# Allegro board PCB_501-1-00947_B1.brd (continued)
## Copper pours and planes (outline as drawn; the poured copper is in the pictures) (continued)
VDD_1V35 on BOTTOM (solid shape): 63.98,92.52 63.99,92.5 64,92.48 64.01,92.45 64.01,92.42 64,92.39 63.98,92.37 63.95,92.35 63.91,92.31 63.88,92.27 63.87,92.25 63.43,91.81 63.09,92.15 63.09,92.48 63.28,92.68 63.28,92.75 62.23,93.81 61.93,93.81 61.62,93.49 61.61,93.49 61.34,93.22 61.28,93.22 60.88,93.62 60.65,93.62 59,91.98 58.71,91.98 58.05,92.63 58.05,92.75 58.15,92.75 59.65,94.24 60.69,94.24 60.69,94.22 60.7,94.17 60.71,94.12 60.74,94.08 60.77,94.04 60.8,94.01 60.84,93.98 60.89,93.96 60.93,93.95 60.98,93.94 61.03,93.94 61.08,93.95 61.13,93.97 61.17,93.99 61.21,94.02 61.24,94.06 61.27,94.1 61.29,94.15 61.3,94.2 61.3,94.24 61.3,94.29 61.29,94.34 61.27,94.39 61.24,94.43 61.21,94.46 61.17,94.5 61.13,94.52 61.08,94.54 61.03,94.55 60.98,94.55 60.93,94.54 60.89,94.53 60.84,94.51 60.8,94.48 60.77,94.45 60.74,94.41 60.71,94.36 60.7,94.32 60.69,94.27 60.69,94.24 59.65,94.24 60.77,95.36 61.13,95.36
VDD_1V35 on TOP: 19.91,73.15 19.27,73.79 19.27,76.33 19.52,76.58 22.06,76.58 22.32,76.33 26.26,76.33 26.76,75.82 26.76,69.34 26.38,68.96 20.41,68.96 19.91,69.47
VDD_1V35 on TOP: 82.64,114.94 85.69,114.94 85.82,115.06 85.82,116.2 85.69,116.33 82.52,116.33 82.39,116.2 82.39,115.19
VDD_1V35 on L3_INT_1: 86.07,113.58 84.72,112.23 82.71,112.23 82.17,111.69 82.17,108.43 81.94,108.2 71.34,108.2 70.58,108.97 70.58,116.31 70.76,116.49 85.77,116.49 86.07,116.19
VDD_1V35 on L4_PWR_1: 38.34,88.95 34.89,85.5 34.89,79.12 25.62,69.85 20.16,69.85 19.78,70.23 19.78,74.42 27.85,82.49 27.85,99.86 39.5,111.51 45.73,111.51 46.26,112.03 55.93,121.71 68.59,121.71 69.73,120.56 75.33,114.97 75.33,100.22 67.74,92.64 66.09,90.98 66.1,90.97 66.1,89.7 65.95,89.56 65.24,89.56 64.66,90.13 57.7,90.13 57.11,90.72 54.42,90.72 52.65,88.95
VDD_1V35_L2 on TOP: 15.08,81.46 15.08,80.9 15.33,80.64 17.24,80.64 17.37,80.77 17.37,81.92 17.32,81.92 16.85,82.39 16.85,82.86 16.49,83.22 16.38,83.46 16.38,84.32 16.18,84.32 16.18,83.09 16.08,82.68 15.91,82.52 15.64,82.52 15.5,82.38 15.5,81.88
VDD_1V35_SNS on TOP: 17.49,80.14 15.21,80.14 15.08,80.01 15.08,74.3 15.46,73.91 18.51,73.91 18.76,74.17 18.76,79.63 18.64,79.76 17.87,79.76
VDD_3V3 on TOP: 32.61,50.93 30.45,50.93 30.19,51.18 30.19,52.83 30.19,52.83 30.19,53.49 30.32,53.62 32.65,53.62 32.73,53.54 32.73,51.05
VDD_3V3 on TOP: 95.85,57.26 90.05,57.26 90.05,59.36 87.3,59.36 87.3,59.46 85.38,59.46 85.38,48.68 95.85,48.68
VDD_3V3 on TOP: 85.82,109.98 84.04,109.98 83.91,109.86 83.91,108.84 83.79,108.71 83.28,108.71 83.15,108.84 83.15,109.86 83.02,109.98 82.9,109.98 82.77,110.11 82.77,111.38 82.9,111.51 83.91,111.51 84.04,111.63 85.69,111.63 85.95,111.38 85.95,110.11
VDD_3V3 on TOP: 119.2,20.57 119.2,21.84 119.2,21.68 120.48,21.68 120.48,21.84 123.16,21.84 123.54,22.22 125.82,22.22 125.95,22.1 125.95,20.83 125.7,20.57 ; 1 cut-out
VDD_3V3 on TOP: 15.59,94.87 14.83,94.87 13.56,93.6 6.57,93.6 6.19,93.98 6.19,98.81 6.7,99.31 15.08,99.31 15.97,98.42 15.97,95.25
VDD_3V3 on TOP: 16.73,6.99 12.67,6.99 12.29,7.37 12.29,30.23 13.17,31.11 17.62,31.11 18.51,30.23 18.51,8.76
VDD_3V3 on BOTTOM: 71.59,56.13 71.59,56.39 72.36,57.15 72.36,59.05 72.23,59.18 72.23,59.94 72.61,60.33 72.61,60.83 72.23,61.21 71.21,61.21 69.18,59.18 69.18,56.64 68.29,55.75 68.29,55.24 69.44,54.1 69.56,54.1
VDD_3V3 on BOTTOM: 21.05,40.26 24.99,40.26 25.49,40.77 25.49,41.78 25.24,42.04 24.1,42.04 23.84,42.29 23.33,42.29 23.33,41.91 23.08,41.66 22.56,41.66 21.93,42.29 21.18,42.29 20.92,42.04 20.92,40.39
VDD_3V3 on BOTTOM: 95.62,57.09 93.52,57.09 93.52,55.85 94.3,55.85 94.3,54.66 94.33,54.66 94.33,53.95 96.59,53.95 96.59,56.03 95.62,56.03
VDD_3V3 on L3_INT_1: 122.65,128.02 123.94,126.72 123.94,119.7 121.2,116.97 107.44,116.97 106.43,115.96 106.43,111.39 105.54,110.51 89.09,110.51 86.85,108.26 82.73,108.26 82.51,108.47 82.51,111.3 83.09,111.88 85.13,111.88 86.64,113.4 86.64,116.44 86.12,116.97 67.4,116.97 62.7,121.67 56.14,121.67 51.48,117.01 50.05,117.01 46.45,113.41 46.45,108.08 45.94,107.57 45.94,101.76 43.62,99.44 43.6,99.44 42.37,98.21 33.09,98.21 30,95.12 30,90.86 29.69,90.55 22.7,90.55 22.04,91.22 22.04,93.68 21.75,93.97 20,93.97 18.7,92.67 14.62,92.67 14.32,92.96 6.82,92.96 5.68,94.11 5.68,111.12 5.68,111.13 5.68,124.6 9.1,128.02
VDD_3V3 on L4_PWR_1: outline of 93 points within 0.83,0.86 129.15,99.95
VDD_3V3 on L5_PWR_2: 97.63,82.8 127.28,82.8 128.19,83.71 128.19,125.03 125.55,127.66 98.37,127.66 96.68,125.97 96.68,83.76
VDD_3V3 on L5_PWR_2: 63.89,51.48 30.66,51.48 30.45,51.69 30.45,59.82 33.75,63.12 33.75,66.69 39.36,66.69 44.67,72.01 44.67,79.92 48.99,84.24 50.46,84.24 52.52,82.19 52.52,81.3 53.17,80.66 55.96,80.66 61.07,75.55 62.56,75.55 70.01,82.99 73.75,79.25 73.75,75.95 77.56,72.14 92.04,72.14 92.3,71.88 92.3,69.22 92.04,68.96 81.37,68.96
VDD_3V3 on L6_INT_2: 39.97,84.71 27.36,84.71 27.02,85.05 27.02,89.53 26.51,90.04 23.72,90.04 23.08,90.68 23.08,93.85 23.84,94.61 33.24,94.61 33.99,93.86 33.99,89.43 34.21,89.21 40.05,89.21 40.23,89.04 40.23,84.96
VDD_3V3 on L6_INT_2: 65.12,83.82 65.75,84.45 65.75,85.47 64.99,86.23 64.74,86.23 63.09,84.58 63.09,83.95 63.21,83.82
VDD_3V3_L4A on TOP: 20.54,90.93 20.54,92.75 20.41,92.88 19.77,92.88 19.68,92.8 19.68,91.43 18.58,90.32 18.58,89.41 19.02,89.41
VDD_3V3_L4B on TOP: 19.09,90.99 19.09,92.78 18.98,92.89 18.2,92.89 18.13,92.82 18.13,90.34 18.18,90.27 18.18,89.41 18.38,89.41 18.38,90.21 18.42,90.28 18.51,90.41
VDD_3V3_LCD on TOP: 22.83,45.97 19.78,45.97 19.14,45.34 16.48,45.34 16.35,45.47 16.35,49.53 15.97,49.91 14.83,49.91 14.44,49.53 14.44,44.45 15.08,43.81 22.83,43.81 23.21,44.2 23.21,45.59
VDD_3V3_LCD on BOTTOM: 19.78,44.96 19.78,46.74 19.91,46.86 22.83,46.86 22.95,46.74 23.09,44.39 23.09,42.19 23,42.1 22.59,42.1 22.15,42.55 21.18,42.55 20.79,42.93 20.79,43.94
VDD_3V3_LCD on L4_PWR_1: 0.98,61.09 0.84,60.94 0.84,38.83 1.57,38.1 15.21,38.1 15.97,38.86 15.97,43.18 15.97,43.18 15.97,45.99 17.11,47.13 17.11,49.02 16.09,50.04 10.68,50.04 9.03,51.69 9.03,60.94 8.89,61.09 ; 1 cut-out
VDD_3V3_PERI on TOP: 28.29,48.51 28.67,48.13 32.22,48.13 32.35,48.26 32.35,50.55 32.22,50.67 30.19,50.67 30.07,50.55 30.07,49.91 29.94,49.78 28.8,49.78 28.29,49.28
VDD_3V3_PERI on TOP: 63.19,40 63.19,38.4 63.52,38.07 66.32,38.07 66.59,38.35 66.59,39.95 66.42,40.12 63.31,40.12
VDD_3V3_PERI on TOP: 106.65,83.06 106.77,83.19 129.36,83.19 129.36,67.93 128.74,67.31 122.65,67.31 122.14,67.82 122.14,70.23 122.65,70.74 123.66,70.74 123.92,70.99 123.92,73.66 123.66,73.91 120.62,73.91 116.93,77.6 108.04,77.6 107.79,77.85 92.32,77.85 91.85,78.31 91.85,82.59 92.32,83.06
VDD_3V3_PERI on BOTTOM: 93.95,81.2 93.95,83.86 93.57,84.24 92.13,84.24 91.99,84.1 91.99,81.18 92.23,80.94 93.69,80.94
VDD_3V3_PERI on L5_PWR_2: 30.03,49.66 30.03,44.36 30.03,44.36 30.25,44.14 45.66,44.14 46.93,42.87 46.93,41.51 48.3,40.13 61.18,40.13 61.82,39.5 61.82,30.31 62.54,29.59 98.65,29.59 98.65,36.73 106.65,36.73 106.65,29.59 127.18,29.59 128.11,30.53 128.11,81.7 127.46,82.35 97.69,82.35 96.35,81 96.35,77.48 95.77,76.9 92.84,76.9 92.55,76.61 92.55,68.83 92.11,68.39 81.56,68.39 63.49,50.31 30.69,50.31
VDD_3V3_SD on TOP: 11.91,87.85 12.1,88.04 12.39,88.04 12.39,88.04 12.87,88.04 12.95,87.95 12.95,87.4 13,87.24 13.08,87.17 13.93,87.17 13.93,86.97 12.72,86.97 12.43,87.26 11.96,87.26 11.91,87.31
VDD_3V3_SNS on TOP: 17.98,89.41 17.78,89.41 17.78,90.22 16.48,91.51 16.48,97.92 16.86,98.3 20.29,98.3 20.54,98.04 20.54,93.98 20.16,93.6 18.64,93.6 18.03,92.99 18.03,90.36 17.98,90.24
VDD_5V on TOP: 4.79,83.06 4.77,83.08 4.77,87.02 4.54,87.25 1.49,87.25 0.98,86.74 0.98,81.66 0.99,81.66 0.99,80.3 1.27,80.01 7.2,80.01 7.52,80.33 7.52,82.2 7.45,82.27 5.58,82.27
VDD_5V on BOTTOM: 10,40.26 10,39.75 9.87,39.62 7.59,39.62 7.46,39.75 7.46,40.51 9.75,40.51
VDD_5V on BOTTOM: 55.5,10.19 57.22,10.19 57.66,10.63 57.66,15.41 57.52,15.56 56.71,15.56 56.58,15.42 56.58,13.05 56.3,12.78 55.5,12.78 55.15,12.43 55.15,10.53
VDD_5V on L5_PWR_2: 1.26,0.96 0.98,1.24 0.98,85.47 0.98,85.47 0.98,87.01 1.13,87.15 4.29,87.15 4.48,86.97 4.48,83.93 4.96,83.46 9.24,83.46 10.38,82.32 10.38,66.92 11.54,65.75 11.54,57.55 10.38,56.39 10.38,44.32 11.14,43.56 23.59,43.56 24.1,43.05 24.1,31.75 25.37,30.48 27.02,30.48 27.65,29.84 27.65,26.29 29.01,24.93 50.17,24.93 54.07,28.83 99.18,28.83 99.18,36.26 106.31,36.26 106.31,29.6 104.75,29.6 104.75,25.93 97.47,25.93 97.47,0.96
VDD_5V_SNS on TOP: 12.95,85.29 12.95,85.57 13.07,85.77 13.93,85.77 13.93,85.97 11.05,85.97 11.05,86.61 5.55,86.61 5.3,86.36 5.3,83.44 5.94,82.8 10.47,82.8
VDD_5V_SNS on TOP: 19.02,86.97 19.02,87.17 19.83,87.17 21.09,88.43 21.74,88.43 22.12,88.81 22.12,88.81 22.19,88.88 23.09,88.88 23.1,88.87 23.1,88.36 23.08,88.33 22.89,88.33 22.85,88.28 22.85,87.14 22.86,87.12 23.02,87.12 23.04,87.1 23.04,86.22 23.03,86.2 21.61,86.2 21.61,87.02 21.39,87.24 20.94,87.24 20.63,86.93 19.92,86.93 19.88,86.97
VDD_5V_SNS on L3_INT_1: 10.35,89.36 20.2,89.36 20.84,89.99 23.11,89.99 23.21,89.9 23.21,85.15 22.8,84.74 22.51,84.74 22.3,84.53 22.3,83.46 21.79,82.95 10.09,82.95 9.99,83.05 9.99,89
VDD_CAN on TOP: 74.39,25.91 72.61,25.91 72.23,26.29 72.23,28.19 72.36,28.32 74.39,28.32 74.52,28.19 74.52,26.04
VDD_DCJACK_5VIN on TOP: 30.45,111.12 20.92,111.12 20.29,111.76 20.29,121.03 20.54,121.28 33.75,121.28 34.13,120.9 34.13,114.81
VDD_DCJACK_5VIN on BOTTOM: 20.29,121.03 20.54,121.28 33.75,121.28 34.13,120.9 34.13,114.81 30.45,111.12 20.92,111.12 20.29,111.76
VDD_DDR_VTT on TOP: 81.88,114.94 80.87,114.94 80.74,115.06 80.74,119.25 80.9,119.41 82.34,119.41 82.41,119.34 82.41,117.79 82.01,117.38 82.01,115.06
VDD_LDO_1V5 on TOP: 29.94,83.82 26.76,83.82 26.64,83.95 26.64,85.72 26.89,85.98 27.27,85.98 27.65,86.36 27.65,87 27.78,87.12 29.94,87.12 30.07,87 30.07,83.95
VDD_LDO_1V5 on BOTTOM: 75.53,116.97 72.36,120.14 49.12,120.14 34.26,105.28 34.26,83.69 33.75,83.19 26.51,83.19 26.13,83.57 26.13,89.15 27.75,90.78 27.75,107.72 44.77,124.73 49.78,124.73 51.29,126.24 68.15,126.24 69.76,127.85 89.22,127.85 90.9,126.17 90.9,113.41 104.36,99.95 110.16,99.95 114.33,95.78 116.08,95.78 116.85,95.01 116.85,88.18 116.81,88.14 108.81,88.14 105,91.95 89.76,91.95 79.09,102.62 79.09,106.81 75.53,110.36
VDD_LDO_1V5 on L3_INT_1: 114.77,82.04 91.79,82.04 91.53,82.3 91.53,84.84 93.95,87.25 100.8,87.25 102.96,89.41 105.31,89.41 111.11,95.2 118.69,95.2 118.84,95.05 118.84,86.11
VDD_LDO_1V5_SNS on TOP: 19.85,85.77 19.02,85.77 19.02,85.97 21.2,85.97 21.3,86.08 21.91,86.08 21.91,86.08 22.75,86.08 22.76,86.08 23.01,86.08 23.15,86.22 23.15,87 23.2,87.06 23.72,87.06 23.78,87.12 27.14,87.12 27.27,87 27.27,86.49 27.07,86.28 26.44,86.28 26.19,86.03 26.19,83.88 26.13,83.82 24.09,83.82 23.19,84.72 20.93,84.72 20.06,85.59
VDD_LDO_2V5 on TOP: 61.56,37.72 61.82,37.97 62.58,37.97 62.96,38.35 62.96,39.94 62.83,40.07 56.09,40.07 55.9,39.88 55.9,37.84 56.02,37.72
VDD_LDO_2V5 on BOTTOM: 28.8,26.04 30.07,26.04 30.19,26.16 30.19,27.69 30.07,27.81 28.16,27.81 28.03,27.69 28.03,26.8
VDD_LDO_2V5 on L5_PWR_2: 60.93,39.12 60.42,39.62 47.59,39.62 46.96,38.99 46.96,31.37 46.08,30.49 28.65,30.49 28.03,29.88 28.03,26.67 29.3,25.4 49.75,25.4 53.94,29.59 60.27,29.59 60.93,30.25
VDD_LDO_2V8 on TOP: 25.37,48.13 27.53,48.13 27.91,48.51 27.91,49.28 27.65,49.53 24.5,49.53 23.46,50.57 22.47,50.57 22.36,50.46 22.36,47.98 22.51,47.83 25.07,47.83
VDD_LDO_2V8 on L6_INT_2: 25.11,40.39 6.82,40.39 6.06,41.15 6.06,45.85 7.33,47.12 10.89,47.12 12.79,45.21 17.11,45.21 21.94,50.04 25.62,50.04 26.51,49.15 26.51,41.78
VDD_LPSR_IN on L5_PWR_2: 67.98,86.09 67.98,85.77 71.99,81.77 73.37,80.39 73.85,80.39 77.11,83.65 77.11,84.23 76.47,84.88 71.51,84.88 70.96,85.42 70.96,86.5 70.74,86.72 68.61,86.72
VDD_PHY_1V0 on TOP: 40.79,37.09 40.86,37.16 40.86,38.83 41.5,39.47 41.5,42.08 41.25,42.33 39.77,42.33 39.69,42.25 39.69,38.98 38.54,37.83 38.54,37.14 38.59,37.09
VDD_PHY_1V0 on BOTTOM: 38.66,37.46 40.49,37.46 40.85,37.81 40.85,38.82 41.17,39.14 41.17,42.22 41.06,42.33 36.94,42.33 36.08,41.46 29.74,41.46 29.29,41.01 29.29,35.85 29.46,35.68 31.11,35.68 31.31,35.88 31.31,39.63 31.89,40.21 34.51,40.21 34.67,40.05 34.67,38.52 34.78,38.41 35.4,38.41 35.58,38.59 38.5,38.59 38.57,38.52 38.57,37.56
VDD_PHY_1V0 on L6_INT_2: 38.19,29.46 30.97,29.46 29.47,30.96 29.47,40.07 30.03,40.64 38.04,40.64 38.32,40.36 38.32,36.48 38.15,36.31 34.76,36.31 34.48,36.02 34.48,33.69 34.72,33.45 38.43,33.45 38.83,33.05 38.83,30.1
VDD_SD on L6_INT_2: 97.12,32.77 97.12,32.77 85.8,32.77 85.27,33.3 85.27,67.51 87.01,69.25 90.21,69.25 90.77,69.81 90.77,70.35 90.77,70.36 90.77,70.93 88.61,73.09 64.7,73.09 62.01,75.79 58.63,75.79 58.56,75.86 58.56,78.67 59.61,79.73 61.17,79.73 61.34,79.56 64.07,79.56 66.86,76.77 100.3,76.77 100.53,76.54 100.53,71.12 100.99,70.67 100.99,65.94 101.57,65.36 107.59,65.36 107.93,65.02 107.93,59.31 107.55,58.93 100.17,58.93 99.66,58.42 99.66,53.34 100.3,52.7 108.17,52.7 109.02,51.85 109.02,32.77
VDD_SD2 on L4_PWR_1: 71.51,78.23 76.17,78.23 79.39,75.01 80.66,75.01 80.88,75.22 80.88,76.16 80.87,76.17 80.87,77.09 77.66,80.3 67.52,80.3 67.26,80.04 64.63,80.04 64.5,79.9 63.97,79.9 63.7,79.63 62.68,79.63 62.09,80.22 62.09,80.9 61.66,81.33 61.27,81.33 60.63,80.69 60.63,79.49 61.45,78.67 61.45,78.22 62.2,77.47 62.2,75.82 62.32,75.69 68.97,75.69
VDD_SD3 on L6_INT_2: 82.47,56.59 82.77,56.9 82.77,70.36 82.39,70.74 78.45,70.74 77.56,69.85 77.56,63.56 76.8,62.8 66.25,62.8 65.93,62.48 65.93,56.77 66.11,56.59
VDD_SD3 on L6_INT_2: 66.64,81.41 67.91,80.14 69.56,80.14 70.58,81.15 70.58,81.66 68.55,83.69 62.41,83.69 61.89,83.17 61.89,81.71 62.19,81.41
VDD_SD_CON on L6_INT_2: 107.79,53.21 100.42,53.21 100.17,53.47 100.17,58.17 100.3,58.29 105.76,58.29 107.92,56.13 107.92,53.34
VDD_SOC_ARM on BOTTOM (solid shape): 62.86,89.24 63.45,89.24 63.5,89.21 63.64,89.06 63.64,88.81 62.7,87.87 62.66,87.87 61.46,89.07 61.46,89.11 60.9,89.67 60.89,89.69 60.89,89.72 60.59,90.16 60.37,89.67 60.38,89.66 60.38,89.62 59.57,88.82 59.17,88.82 58.17,89.82 58.17,90.12 58.29,90.23 58.3,90.25 58.33,90.25 58.5,90.28 58.63,90.4 58.65,90.42 58.67,90.43 58.78,90.43 59.51,91.16 59.66,91.16 59.83,90.98 59.89,90.98 59.91,90.98 59.93,90.96 60.19,90.83 60.44,90.99 60.44,90.99 60.51,91.06 60.51,91.17 60.71,91.37 60.73,91.37
VDD_SOC_ARM on TOP: 27.65,83.31 27.91,83.57 35.27,83.57 36.16,82.68 36.16,75.06 53.56,57.66 53.56,52.07 43.72,42.23 43.72,41.22 43.51,41.01 41.87,41.01 41.74,41.15 41.74,44.82 42.64,45.72 48.61,51.69 48.61,57.78 43.91,62.48 37.94,62.48 29.05,71.37 29.05,76.71 27.65,78.11
VDD_SOC_ARM on L5_PWR_2: 32.1,80.27 32.1,94.61 33.88,96.39 48.02,96.39 53.17,91.24 53.18,91.24 53.87,90.55 55.59,90.55 60.67,95.63 61.43,95.63 67.42,89.65 67.42,85.49 69.51,83.39 69.51,82.88 62.45,75.82 61.31,75.82 55.98,81.15 53.35,81.15 53.03,81.47 53.03,82.39 50.66,84.77 48.8,84.77 44.04,80.01 44.04,76.11 43.46,76.11 42.6,75.26 42.6,74.93 44.04,73.5 44.04,71.88 39.21,67.06 33.75,67.06 33.37,67.44 33.37,78.99
VDD_SOC_ARM_L1 on TOP: 18.58,84.33 18.58,83.37 19.65,82.3 19.66,82.3 20.39,81.56 21.59,81.56 21.68,81.65 21.68,83.49 21.6,83.57 19.87,83.57 19.12,84.33
VDD_SOC_ARM_SNS on TOP: 22.06,83.45 22.06,78.49 22.19,78.36 27.02,78.36 27.27,78.61 27.27,83.44 27.1,83.61 22.22,83.61
VDDA_1P8 on BOTTOM: 78.36,83.63 78.94,83.06 79.6,83.06 79.88,83.34 79.88,84.56 79.68,84.75 77.58,84.75 77.14,85.18 76.28,85.18 76.22,85.12 76.22,84.63 77.22,83.63
VDDA_1P8 on L4_PWR_1: 86.83,99.46 86.53,99.76 75.36,99.76 66.48,90.88 66.48,88.71 66.07,88.31 66.07,83.73 66.22,83.58 86.62,83.58 86.83,83.79
VDDA_ADC_1P8 on BOTTOM: 79.55,86.66 79.55,85.7 79.01,85.17 77.74,85.17 77.31,85.6 76.55,85.6 75.48,84.53 73.45,84.53 73.35,84.63 72.18,84.63 71.57,84.02 71.54,84.02 70.48,85.09 70.48,86.72 70.99,87.22 72.94,87.22 72.94,86.31 73.07,86.18 73.96,86.18 74.19,86.41 73.94,86.65 73.94,87.44 74.44,87.93 75.61,87.93 76.47,87.07 79.14,87.07
VDDA_ADC_1P8 on L5_PWR_2: 71.28,85.46 71.84,84.9 73.93,84.9 74.6,85.57 76.35,85.57 77.02,84.9 78.4,84.9 78.87,85.37 78.87,87.49 78.25,88.11 71.75,88.11 71.28,87.63
VDDA_CLKGEN_1V8 on BOTTOM: 79.84,94.74 80.1,94.74 80.23,94.61 80.23,93.22 80.1,93.09 79.33,93.09 76.13,96.29 76.13,96.53 77.21,97.61 77.27,97.61 78.39,96.49 78.39,96.19
VDDA_PHY_1P8 on BOTTOM (solid shape): 67.62,87.93 67.62,87.82 67.03,87.23 66.87,87.23 65.5,88.59 65.1,88.59 64.83,88.86 64.83,89.05 65.26,89.47 65.31,89.47 65.51,89.67 65.87,89.67
VDDA_PHY_1P8 on L6_INT_2: 59.18,84.15 60.12,83.21 61.73,83.21 63.83,85.31 63.83,85.85 65.33,87.34 67.3,87.34 67.61,87.66 67.61,88.07 67.6,88.08 67.6,88.59 65.82,90.38 64.53,90.38 60.25,86.09 60.25,85.81 59.18,84.74
VDDD_1P0_CAP on L3_INT_1: 63.59,90.3 64.08,90.79 66.15,90.79 67.66,89.28 67.66,87.63 67.02,87 60.74,87 58.96,85.22 56.74,85.22 56.21,85.75 56.21,89.94 56.56,90.3
VDDIO_PHY_3V3 on L5_PWR_2: 45.66,43.36 46.32,42.69 46.32,31.88 45.56,31.11 25.62,31.11 24.99,31.75 24.99,42.7 25.64,43.36
BASE_PNP on TOP: 6.19,101.35 7.59,101.35 7.97,101.73 7.97,103.12 8.86,104.01 9.75,104.01 9.87,104.14 9.87,104.39 9.75,104.52 8.09,104.52 7.97,104.39 6.06,104.39 5.94,104.27 5.94,101.6
BAT_IN on TOP: 7.2,128.99 13.28,128.99 13.56,128.71 13.56,119.25 13.17,118.87 10.13,118.87 10,118.75 10,118.72 9.84,118.56 9.84,118.2 9.76,118.13 6.89,118.13 6.82,118.19 6.82,128.62
BUCK_FB_L on TOP: 122.65,65.61 122.65,65.21 122.67,65.19 123.24,65.19 123.48,65.09 124.3,64.26 127.47,64.26 127.73,64.52 127.73,66.29 127.47,66.55 124.3,66.55 123.52,65.77 123.21,65.63 122.67,65.63
CC_RES on TOP: 96.49,105.79 99.53,105.79 99.66,105.92 99.66,116.71 95.34,121.03 88.74,121.03 88.61,120.9 88.61,116.71 90.64,114.68 90.64,113.16 90.9,112.9 95.98,112.9 96.36,112.52 96.36,105.92
DDR_VREF on TOP: 77.69,109.98 77.69,111.25 77.82,111.38 80.23,111.38 80.36,111.51 80.99,111.51 80.99,110.11 80.74,109.86 77.82,109.86
DDR_VREF on L5_PWR_2: 66.42,91.56 66.16,91.56 61.48,96.25 60.48,96.25 55.41,91.19 54.87,91.19 48.39,97.66 48.39,117.34 51.88,120.82 70.28,120.82 75.36,115.74 79.65,111.46 79.65,109.57 79.12,109.05 76.87,109.05 76.22,108.4 76.22,101.37
DEBUG_5V0 on TOP: 120.73,101.77 121.92,101.77 122.19,102.04 122.19,106.45 121.93,106.71 120.67,106.71 120.53,106.57 120.53,101.97
DEBUG_5V0 on L6_INT_2: 114.01,94.61 126.84,94.61 127.98,95.76 127.98,120.02 125.57,122.43 95.98,122.43 95.22,121.67 95.22,109.35 95.85,108.71 99.92,108.71
DEBUG_5V0_USB on TOP: 122.46,105.28 123.03,105.28 123.54,105.79 124.81,105.79 125.32,106.3 126.71,106.3 126.84,106.43 126.84,107.06 126.71,107.19 124.81,107.19 124.17,106.55 122.45,106.55 122.4,106.5 122.4,105.35
FUSE_FSOURCE on L6_INT_2: 65.53,86.7 65.53,85.91 67.39,84.06 72.02,84.06 72.61,83.47 74.16,83.47 76.46,81.17 78.84,81.17 79.5,81.82 79.5,83.35 74.58,88.27 68.98,88.27 67.66,86.94 65.77,86.94
OTG_VBUS on TOP: 47.08,6.99 49.37,6.99 49.62,6.73 50.26,6.73 50.51,6.99 50.51,8.38 50.26,8.64 48.48,8.64 48.35,8.76 48.35,10.54 48.23,10.67 47.08,10.67 46.96,10.54 46.96,7.11
OTG_VBUS on BOTTOM: 46.94,8.33 48.24,8.33 48.47,8.56 48.47,9.16 50.21,10.9 50.21,16.6 50.12,16.7 49.08,16.7 48.97,16.59 48.97,12.62 46.87,10.51 46.87,8.39
PMIC_PWR on TOP: 18.76,106.93 8.6,106.93 8.22,106.55 8.22,104.9 7.97,104.65 5.05,104.65 4.54,105.16 4.54,107.19 5.05,107.7 5.05,112.14 4.54,112.65 4.54,117.85 4.67,117.97 19.53,117.97 19.65,117.85 19.65,107.82
PMIC_PWR on TOP: 20.04,88.97 19.02,88.97 19.02,89.24 19.9,90.13 19.91,90.13 20.44,90.66 20.65,90.66 20.72,90.59 20.72,89.65
PMIC_PWR on TOP: 19.93,83.67 19.04,84.57 19.02,84.57 19.02,84.77 20.05,84.77 20.8,84.02 20.8,83.67
PMIC_PWR on TOP: 13.07,86.17 13.93,86.17 13.93,86.37 13.06,86.37 12.59,86.45 12.23,86.8 11.17,86.8 11.17,86.07 12.98,86.07
PMIC_PWR on TOP: 19.84,86.57 19.02,86.57 19.02,86.77 19.87,86.77 19.94,86.84 20.64,86.84 20.96,87.15 21.34,87.15 21.49,87 21.49,86.45 21.45,86.41 20,86.41
PMIC_PWR on TOP: 13.45,83.46 12.08,82.09 11.65,82.09 11.26,82.47 11.26,83.01 13.02,84.77 13.93,84.77 13.93,84.57 14.18,84.32 14.38,84.32 14.38,83.46
PMIC_PWR on TOP: 16.58,83.29 16.58,84.32 16.78,84.32 16.78,83.62 16.78,83.62 16.78,83.48 17.13,83.27 17.65,82.75 17.65,82.35 17.55,82.25 17.15,82.25 16.96,82.43 16.96,82.91
PMIC_PWR on TOP: 118.46,60.58 118.46,64.52 119.22,65.28 119.85,65.28 120.11,65.53 121.12,65.53 121.25,65.41 121.25,63.88 121.12,63.75 121.12,60.58 120.87,60.33 118.71,60.33
PMIC_PWR on BOTTOM: 14.16,84.31 13.68,84.79 13.68,85.05 13.64,85.09 12.95,85.09 12.68,85.36 12.68,86.88 12.55,87.01 8.97,87.01 8.88,86.93 8.88,82.24 8.95,82.17 17.62,82.17 17.63,82.18 19.41,82.18 20.86,83.79 20.86,84.98 20.47,85.38 20.47,86.33 20.6,86.45 21.95,86.45 22.05,86.56 22.05,88.57 21.96,88.66 21.62,88.66 21.43,88.85 21.43,90.1 21.35,90.18 20.9,90.18 20.54,90.53 20.54,92.58 20.29,92.84 18.89,92.84 18.76,92.71 18.76,87.88 19.06,87.58 19.06,84.89 18.25,84.08 17.25,84.08 17.02,84.31
PMIC_PWR on L4_PWR_1: 45.41,112.09 54.78,121.46 54.91,121.46 55.71,122.26 68.81,122.26 75.92,115.14 75.92,100.83 76.37,100.39 86.78,100.39 87.37,99.8 87.37,84.36 87.61,84.11 91.56,84.11 92.05,83.62 92.05,68.36 92.26,68.15 112.59,68.15 113.27,67.47 113.27,59.07 113.49,58.85 129.03,58.85 129.13,58.95 129.13,128.83 128.78,129.17 1.37,129.17 0.93,128.74 0.93,101.27 1.62,100.58 27.47,100.58 38.97,112.09
PMIC_PWR on L5_PWR_2: 4.45,87.5 1.17,87.5 0.96,87.72 0.96,125.11 3.33,127.48 21.91,127.48 22.32,127.07 22.32,82.16 21.82,81.66 11.65,81.66 9.53,83.79 5.17,83.79 4.82,84.14 4.82,87.14
PSU_5V0 on TOP: 20.79,110.62 20.02,109.84 20.02,107.78 19.03,106.78 11.2,106.78 11.14,106.72 11.14,105.16 9.75,103.76 8.98,103.76 8.86,103.63 8.86,102.87 9.36,102.36 9.36,100.46 10,99.82 15.21,99.82 16.48,98.55 21.18,98.55 21.3,98.68 28.41,98.68 29.68,99.95 31.34,99.95 31.97,99.31 31.97,97.54 32.35,97.16 32.35,96.01 32.48,95.89 33.75,95.89 34,96.14 34,103.68 33.68,104 30.19,104 29.31,104.89 29.31,110.31 29,110.62
PWR_OVP_LED on TOP: 44.04,101.85 44.04,107.44 43.65,107.82 40.73,107.82 40.23,107.31 40.23,101.35 40.35,101.22 43.4,101.22
USB_HOST_VBUS on BOTTOM: 42.13,6.48 42.13,9.02 41.11,10.03 41.11,13.84 41.37,14.1 43.4,14.1 43.65,13.84 43.65,9.91 44.42,9.14 46.13,9.14 46.18,9.09 46.18,8.09 46.27,8.01 48.74,8.01 48.81,8.08 48.81,9.09 48.86,9.14 58.26,9.14 59.53,10.41 59.53,12.7 59.15,13.08 59.15,15.62 59.54,16.01 62.44,16.01 62.58,15.88 62.58,6.1 61.94,5.46 43.91,5.46 43.02,6.35 42.26,6.35
USB_OTG_PWR on TOP: 51.27,3.43 52.42,3.43 52.54,3.56 52.54,5.21 51.66,6.1 51.66,7.62 51.4,7.87 51.02,7.87 50.77,7.62 50.77,3.94
USB_OTG_VBUS on BOTTOM: 50.45,14.04 50.66,14.25 54.82,14.25 54.99,14.41 54.99,17.01 55.27,17.29 62.45,17.29 62.58,17.16 62.58,16.55 62.34,16.32 56.47,16.32 56.34,16.19 56.34,13.12 56.16,12.94 55.37,12.94 54.91,12.48 54.91,12.07 54.78,11.94 50.52,11.94 50.45,12.01
VSNVS on TOP: 93.69,93.6 91.79,93.6 91.66,93.73 91.66,95.76 91.79,95.89 92.55,95.89 92.68,95.76 92.68,94.74 92.93,94.49 94.07,94.49 94.58,95 94.58,97.54 96.36,99.31 96.36,105.41 96.49,105.54 99.53,105.54 99.66,105.41 99.66,93.73 99.41,93.47 93.82,93.47

Small or netless copper shapes (teardrops, artwork), in the pictures only: 66 on TOP, 124 on BOTTOM

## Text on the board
BOTTOM: P/N:501-1-00947_B1
Package Geometry/Pastemask Bottom: "FIDUCIAL'S  WILL NOT BE THRU OPEN, IT SHOULD BE HALFETCH".
Ref Des/Silkscreen Bottom: mPCIE | LCD
User.Comments: DESIGNED FOR: TIXU_MX7D | PART NO: | PARTNAME: | 501-1-00947 | TIXU_MX7D, EVAL BOARD | REV:B1 | LAYER: | SHEET :       OF 15 | ALL DIMENSIONS ARE IN MM | TOLERANCE + / - 0.1MM | EXAMPLE FEATURE: | AREA FREE OF SOLDERMASK
Package Geometry/Pastemask Top: "FIDUCIAL'S  WILL NOT BE THRU OPEN, IT SHOULD BE HALFETCH".
Ref Des/Silkscreen Top: R | 5V | MIPI CSI | 3V3 | PWM LED | GND | 1V8 | ENET | P1 | P2 | 2V8 | INTERNAL BOOT------ | FUSE--------------- | RESERVED----------- | SERIAL DOWNLOADER-- | 1V35 | BOOT_MODE_SW3 | 1V5 | -------- | OVER | 1V | ON | VOLTAGE | LED | PWR UP | 0  0 | 0  1 | 1  0 | 1  1 | USB HOST | OFF | BOOT_MODE_SW2 | eMMC 01010000 | SD   00100000 | QSPI 10000000 | 2V5 | UART | CAN | MIC | P/N:501-1-00947_B1 | SPK OUT | SIM | ON/OFF | FUNC1 | VDD_SD | JTAG | HP OUT | PERI_3V3 | FUNC2 | PMIC LED | BAT | USB OTG | -KEEP KEY DOWN- | RST | DEBUG
L2_GND_1: L2_GND1 | 2
L3_INT_1: L3_INT1 | 3
L4_PWR_1: L4_PWR_1 | 4
L5_PWR_2: L5_PWR_2 | 5
L6_INT_2: L6_INT_2 | 6
L7_GND_2: L7_GND_2 | 7
COMPVAL_TYPE_BOTTOM: TOOLING HOLES 3.20 MM | (4 PLACES) | PANEL FIDUCIAL | (TOP AND BOTTOM) | (3 PLACES)
User.10: DESIGNED FOR: TIXU_MX7D | PART NO: | PARTNAME: | 501-1-00947 | TIXU_MX7D, EVAL BOARD | REV:B1 | LAYER: | SHEET :       OF 3 | PANEL TOP | 2 | ALL DIMENSIONS ARE IN MM | TOLERANCE + / - 0.1MM | PANEL_TOP | ALL DIMENSIONS ARE IN MILLIMETERS
User.11: 3 | PANEL BOT | SHEET :       OF 3 | LAYER: | REV:B1 | TIXU_MX7D, EVAL BOARD | 501-1-00947 | PART NO: | PARTNAME: | DESIGNED FOR: TIXU_MX7D | TOLERANCE + / - 0.1MM | ALL DIMENSIONS ARE IN MM | PANEL_BOTTOM
User.14: DESIGNED FOR: TIXU_MX7D | PART NO: | PARTNAME: | 501-1-00947 | TIXU_MX7D, EVAL BOARD | REV:B1 | LAYER: | SHEET :       OF 15 | PANEL | 15 | ALL DIMENSIONS ARE IN MM | TOLERANCE + / - 0.1MM
User.16: FIGURE | FINISHED_SIZE | 8.0 | 10.0 | 12.0 | 20.0 | 28.0 | 35.0 | 36.0 | 40.0 | 41.0 | 43.0 | 53.0 | 62.0 | 63.0 | 125.0 | 126.0 | 44.0 | 56.0 | 67.0 | 105.0 | 128.0 | 47.0x20.0 | 91.0x39.0 | 98.0x39.0 | 118.0x39.0 | DRILL CHART: TOP to BOTTOM | ALL UNITS ARE IN MILS | TOLERANCE_DRILL | +3.0/-3.0 | PLATED | NON-PLATED | QTY | 605 | 1669 | 350 | 2 | 3 | 14 | 6 | 16 | 10 | 4 | 1 | 2712 | TOTAL HOLES:
User.18: DESIGNED FOR: TIXU_MX7D | PART NO: | PARTNAME: | 701-1-01125 | TIXU_MX7D, EVAL BOARD | REV:B1 | LAYER: | SHEET :       OF 3 | ASSEMBLY | 1 | ALL DIMENSIONS ARE IN MM | TOLERANCE + / - 0.1MM | PCB SECONDARY SIDE | MAXIMUM HEIGHT 6.949 MM | PCB PRIMARY SIDE | MAXIMUM HEIGHT 14.699 MM | INITIAL RELEASE | SCHEMATIC UPDATE | B | A | D | C | ASY 501-1-00947-B1 CONSISTS OF FOLLOWING ASSEMBLY DATA | 501-1-00947-B1_PMT .ART -  TOP PASTE (TOP PASTE) | 501-1-00947-B1_PNP .TXT -  PICK AND PLACE DATA | 501-1-00947-B1_PMB .ART -  BOTTOM PASTE (BOTTOM PASTE) | 2 | 3 | 4 | 5 | NOTES:          UNLESS OTHERWISE SPECIFIED. | CAUTION :       COMPONENTS ARE SUBJECT TO DAMAGE BY STATIC ELECTRICITY. | 7) STICK TO THE BACKING REQUIREMENT AS PER CLASS RECOMMENEDATION. | 8) "FIDUCIAL'S  WILL NOT BE THRU OPEN, IT SHOULD BE HALFETCH". | 2) LABELS SHALL NOT TO BE PLACED OVER EXPOSED COPPER AND METAL. | 3) SOLDER PASTE TOOLING SHOULD BE MADE USING 501-1-00947-B1_PMT.ART FOR PRIMARY SIDE. | 5) APERTURES MAY BE MODIFIED TO BEST FIT VVDN REQUIREMENT. | 6) ASSEMBLY SHALL BE ELCECTRICALLY TESTED. | 1) SOLDER AND ASSEMBLE AS PER INDUSTRY WORKMANSHIP STANDARDS. | 4) SOLDER PASTE TOOLING SHOULD BE MADE USING 501-1-00947-B1_PMB.ART FOR SECONDARY SIDE. | 6 | 7 | 8
User.19: UPDATED MANUALLY | NEEDS TO BE | APCB, DS,TIXU_MX7D, EVAL BOARD | ASY NUMBER: | VVDN TECHNOLOGIES PVT.LTD. | 701-1-01125-B1 | REV | A1 | B1 | 19-JUN-19 | 30-OCT-19 | DATE | REVISION NOTES | PCBA ASSEMBLY DRAWING | TITLE: | PCB_DESIGNER | VVDN
User.20: LAYER STACKUP DETAILS | SOLDER MASK | 0.8 mil | 3.3  mil, PREPEG | L1_TOP Cu, 0.333oz +Plating | L2_SIG1 Cu,1oz | 7.87 mil, CORE | L3_GND1 Cu, 1oz | 5.8 mil, PREPEG | 16.14 mil, CORE | L4_SIG2 Cu,1oz | L6_PWR1 Cu, 1oz | L5_GND2 Cu,1oz | L7_PWR2 Cu, 1oz | 3.3 mil, PREPEG | L8_BOTTOM Cu, 0.333oz +Plating | 1.6MM | TOL. +\- 10% | LAYER NAME | L8_BOTTOM | L1_TOP | L3_SIG1 | L6_SIG2 | SINGLE ENDED | 5.4 MILS | 5.0 MILS | WIDTH | 50 OHM | 4.1 MILS | 4.6 MILS | DIFFERENTIAL 100 OHM | 6.4 MILS | 6.9 MILS | SPACING | 5 MILS | DIFFERENTIAL 90 OHM | ---- | 5.7 MILS | DIFFERENTIAL 85 OHM | 6.1 MILS | B1 | 30-OCT-19 | SCHEMATIC UPDATE | VVDN | 19) | 12) | 13) | 14) | 15) | 20) | 18) | 10) | 16) | 17) | 11) | SST_ | SMT_ | FAB_ | FAB_501-1-00947_B1.ZIP CONSISTS OF | 3) | PMT_ | 4) | L8_BOT_ | L1_TOP_ | L7_GND2_ | L2_GND1_ | L3_INT1_ | L6_INT2_ | 5) | L4_PWR1_ | L5_PWR2_ | 6) | 8) | 9) | 7) | ART_APER_ | IPC_ | ART_PARAM_ | NC_TOOLS_ | NC_PARAM_ | RFQ_ | ROU_1-8_501-1-00947_B1 | SMB_ | SSB_ | PNL_ | PMB_ | DRL_1-8_501-1-00947_B1 | 501-1-00947_B1 | APPLY LPI GREEN SOLDER MASK TO INDICATED SIDES OVER BARE COPPER. | LAYER TO LAYER REGISTRATION SHALL BE WITHIN 0.08 FIM. | SILKSCREEN SHOULD BE WITH WHITE, NON-CONDUCTIVE EPOXY INK. | BOARD THICKNESS WHICH EVER MENTIONED IS WITH PLATING. | MARK WITH VENDOR LOGO AND DATE CODE. MUST NOT BE ETCHED. | FABRICATE TO THE REQUIREMENTS OF IPC-A-600. | ETCH PER GERBER FILES L1_TOP_501-1-00947_B1.ART THRU L8_BOT_501-1-00947_B1.ART | LABELING SHALL NOT BE PLACED OVER EXPOSED COPPER. | THERE ARE IMPEDANCE CONTROLED SIGNALS RUNNING INSIDE BOARD. | ALL COMPONENT AND MATERIAL USED ARE PB FREE AND ROHS COMPLAINT. | VENDOR SHOULD NOT MODIFY ARTWORK EXCEPT FOR PROCESS CONTROL. | HANDLE, PACKAGE, AND SHIP CAREFULLY THAT TO ENSURE NO DAMAGE. | BOARD SHOULD BE 100% ELECTRICALLY TESTED FOR OPEN AND SHORT CIRCUIT. | REFER TO PANEL DRAWING FOR PANEL DETAILS. | FAB HOUSE MUST PROVIDE WORKING GERBERS AND STACK UP REPORT FOR SIGN OFF. | ALL HOLE DIAMETER TO BE  +/-0.075mm  UNLESS OTHERWISE SPECIFIED. | ALL HOLE DIAMETERS  ARE FINISHED SIZE. | BOW AND TWIST SHALL NOT EXCEED 0.75% OR AS PER  IPC APPLICABLE CLAUSE. | MANDATORY BAKE REQUIREMENT MUST BE MENTIONED IN THE PACKING BOX. | .ART     -     SOLDERMASK TOP | .ART     -     SOLDERPASTE TOP | .ART     -     SILKSCREEN TOP | .PDF     -     FABRICATION DRAWING | .ART -     SOLDERMASK BOTTOM | .ART -     SILKSCREEN BOTTOM | .ART -     PANEL DRAWING | .ART -     SOLDERPASTE BOTTOM | .IPC -     IPC 365 NETLIST | .XlS -     RFQ DOCUMENT | .ART  -     LAYER 01 (TOP SIDE) | .ART -     LAYER 08 (BOTTOM SIDE) | .ART -     LAYER 02 (INNER PLANE1) | .ART -     LAYER 03 (INNER SIGNAL1) | .ART -     LAYER 04 (INNER PLANE2) | .ART -     LAYER 05 (INNER PLANE3) | .ART -     LAYER 06 (INNER SIGNAL2) | .ART -     LAYER 07 (INNER PLANE4) | .ROU -     NC ROUTE FILE | .TXT -   NC TOOLS REPORT | .TXT -   NC DRILL PARAMETERS | .DRL -     NC DRILL_1-8 | .TXT -  ART APERTURE | .TXT -  ART PARAMETER | FR4 TG 170 | DETAIL A | (0,0)
User.21: IMPEDANCE REQUIREMENT | IMPEDANCE TABLE | BPCB, 8L, 130x130mm,
User.22: DESIGNED FOR: TIXU_MX7D | PART NO: | PARTNAME: | 501-1-00947 | TIXU_MX7D, EVAL BOARD | REV:B1 | LAYER: | SHEET :       OF 3 | FAB | 1 | ALL DIMENSIONS ARE IN MM | TOLERANCE + / - 0.1MM
User.23: L1_TOP | 1
User.30: L8_BOT | 8
User.31: PMT | 10
User.32: PMB | 9
User.33: SMT | 12
User.34: SMB | 11
User.35: SST | 14
User.36: SSB | 13
User.45: DESIGNED FOR: TIXU_MX7D | PART NO: | PARTNAME: | 701-1-01125 | TIXU_MX7D, EVAL BOARD | REV:A1 | LAYER: | SHEET :       OF 3 | VARIANT TOP | 2 | 3 | VARIANT BOT | REV:B1 | ASSSYEMBLY TOP | ALL DIMENSIONS ARE IN MM | TOLERANCE + / - 0.1MM | FIGURE | FINISHED_SIZE | 102.0 | DRILL CHART: BOTTOM to BOTTOM | ALL UNITS ARE IN MILS | TOLERANCE_DRILL | +3.0/-3.0 | PLATED | QTY | 4 | TOTAL HOLES:
